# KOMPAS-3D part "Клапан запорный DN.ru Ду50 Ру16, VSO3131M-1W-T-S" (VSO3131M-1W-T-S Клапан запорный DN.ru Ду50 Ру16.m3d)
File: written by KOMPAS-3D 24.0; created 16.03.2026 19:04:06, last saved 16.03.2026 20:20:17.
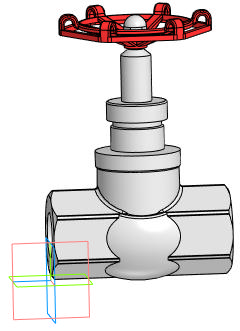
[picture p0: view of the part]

Document properties: Автор: artiomk228874@gmail.com; Полное имя файла: VSO3131M-1W-T-S Клапан запорный DN.ru Ду50 Ру16.cdw

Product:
- Body: Тело 1  | qty 1
    Масса: 2.2329
- Part/product: Клапан запорный DN.ru Ду50 Ру16  | designation VSO3131M-1W-T-S
    Масса: 1.64
    Раздел спецификации: Прочие изделия
    Форматы листов документа: A3
    Примечание: D100-03674
    additional columns: 94d3474e-3e6e-4ddd-ad0b-ef51eb5e31da; VSO3131M-1W-T-S; Клапан запорный DN.ru Ду32 Ру16; Сталь 10 ГОСТ 1050-2013; artiomk228874@gmail.com; c; Шероховатость не задана; Да

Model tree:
1. Операция без истории:1

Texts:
  VSO3131M-1W-T-S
